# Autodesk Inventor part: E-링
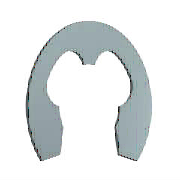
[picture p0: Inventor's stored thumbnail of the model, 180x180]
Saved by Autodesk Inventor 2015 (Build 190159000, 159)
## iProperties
IsCustomPart: 1
Created: 2012-02
Part Number: E-링
Material: 강철, 연강
Description: 일반용 테이퍼 및 줄어든 횡단면 리테이닝 링 - E-링 외부 시리즈 3CM1 리테이닝 링
Document SubType Name: Modeling
Standard: ANSI B27.7
Designer: mduedu
Standard Revision: 1999
Standards Organization: ANSI
Language: ko-KR
Size Designation: 6
Categories: <MemberInstance><Categories><Category DisplayName="샤프트 부품" InternalName="7f7aeb1f-a693-4053-b835-cee3144e0d98" Mnemonic="SHFT"><Category DisplayName="써클립" Inter
Density: 1 g/cm^3
Appearance: 기본값
Author: mduedu
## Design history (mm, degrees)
sketch "스케치1"
  geometry: L1 (-0.485, 0.024)-(0, 0.024) reference; L2 (-3.206, 0)-(3.486, 0) reference; L3 (-2.223, -3.946)-(2.223, -3.946); L4 (0, 1.949)-(0, -3.479) reference; L5 (-2.91, -2.006)-(-2.435, -2.006); L6 (-0.485, -0.066)-(-0.485, 0.405); L7 (0, 2.574)-(2.53, 2.574); L8 (-2.223, -3.946)-(-3.022, -6.291); L9 (0, -0.551)-(-1.278, -0.551); L10 (2.223, -3.946)-(3.022, -6.291); L11 (2.91, -2.006)-(2.435, -2.006); L12 (0.485, -0.066)-(0.485, 0.405); C1 r 3 at (0, -2.976); A1 r 2.425 centre (0, -2.976) between (-2.297, -2.199) and (-2.223, -3.946); A2 r 0.485 centre (0, -0.066) between (-0.485, -0.066) and (0.485, -0.066); A3 r 5.55 centre (0, -2.976) between (4.27, -6.521) and (-4.27, -6.521); A4 r 3.88 centre (0, -2.976) between (-0.97, 0.78) and (-3.424, -1.15); A5 r 0.388 centre (-0.873, 0.405) between (-0.485, 0.405) and (-0.97, 0.78); A6 r 0.582 centre (-2.91, -1.424) between (-3.424, -1.15) and (-2.91, -2.006); A7 r 0.145 centre (-2.435, -2.152) between (-2.297, -2.199) and (-2.435, -2.006); A8 r 0.727 centre (-3.711, -6.057) between (-4.27, -6.521) and (-3.022, -6.291); A9 r 0.727 centre (3.711, -6.057) between (3.022, -6.291) and (4.27, -6.521); A10 r 2.425 centre (0, -2.976) between (2.223, -3.946) and (2.297, -2.199); A11 r 0.145 centre (2.435, -2.152) between (2.435, -2.006) and (2.297, -2.199); A12 r 0.582 centre (2.91, -1.424) between (2.91, -2.006) and (3.424, -1.15); A13 r 3.88 centre (0, -2.976) between (3.424, -1.15) and (0.97, 0.78); A14 r 0.388 centre (0.873, 0.405) between (0.97, 0.78) and (0.485, 0.405); 1 further point
  constraints: 30 point on circle, 20 end point, 15 centre point, 13 symmetric about line, 12 tangent, 8 point on line, 4 parallel, 2 coincident, 2 horizontal, 1 concentric, 1 perpendicular, 1 vertical alignment, 9 other
  dimensions: "d0" = 6 diameter of C1 (= WD); "d3" = 0.97 distance from line of A1.centre L3 (= 0.2 x ND); "d4" = 0.485 radius of A2 (= 0.1 x ND); "d5" = 11.1 diameter of A3 (= SD2); "d8" = 3.88 radius of A4 (= 0.8 x ND); "d9" = 0.97 distance from line of A1.centre L5 (= 0.2 x ND); "d10" = 0.388 radius of A5 (= 0.08 x ND); "d11" = 0.582 radius of A6 (= 0.12 x ND); "d12" = 0.1455 radius of A7 (= 0.03 x ND); "d13" = 0.7275 radius of A8 (= 0.15 x ND); "d14" = 2.425 distance from line of A1.centre L9 (= 0.5 x ND); "d15" = 2.425 radius of A1 (= 0.5 x ND)
extrude "본체" new body sketch "스케치1" distance "d16" = 0.6 (= SD); taper "d17" = 0 deg
workaxis "Work Axis1"
workaxis "Work Axis2"
workplane "Work Plane1"
body "Solid1"
other parameters: "ND" = 4.85 [user parameter; used in 14 equation terms], "SD" = 0.6 [user parameter; used in 1 equation term], "WD" = 6 (= WDMIN) [user parameter; used in 1 equation term], "d1" = 7.76 (= 1.6 x ND), "d2" = 4.85 (= ND), "SD2" = 11.1 [user parameter; used in 1 equation term], "d6" = 4.85 (= ND), "d7" = 0.7275 (= 0.15 x ND), "d18" = 0, "d19" = 0, "d27" = 0, "d28" = 0, "WDMIN" = 6 [user parameter; used in 1 equation term], "SNB" = 0.7 [user parameter], "WDMAX" = 7 [user parameter], "BUBRMI" = 1.2 [user parameter]
